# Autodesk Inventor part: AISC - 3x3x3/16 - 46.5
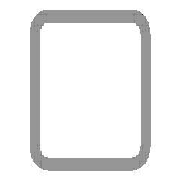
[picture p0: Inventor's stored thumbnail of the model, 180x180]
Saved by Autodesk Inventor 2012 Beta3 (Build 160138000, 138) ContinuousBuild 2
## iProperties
IsCustomPart: 1
Created: 2011-01
Part Number: AISC - 3x3x3/16 - 46.5
Material: Steel, Mild
Description: Tube
Document SubType Name: Modeling
Standard: ANSI
Designer: Beta-8540w
Standards Organization: ANSI
Language: en-US
Size Designation: 3x3x3/16
Categories: <MemberInstance><Categories><Category DisplayName="Structural Shapes" InternalName="089c4875-fa83-4c05-b084-43b9cc11f5ed" Mnemonic="GRDR"><CategoryParameter Dis
Stock Number: 3x3x3/16
Density: 7.86 g/cm^3
_CCFamilyMember: 9
_CCFamilyDisplayName: ANSI AISC (Square) - Tube
_FrameMemberDoc: Frame Member File
_Version: 15.0.0
_GetPNFromCC: 1
G_L: 46.500 in
G_W: 3.000 in
G_H: 3.000 in
+5DFD71D6-FECD-495E-A9B7-A5DCA39C5D65+CUTDETAIL1: Notch
Author: Beta-8540w
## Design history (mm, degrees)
node "Start plane"
node "End plane"
sketch "Sketch"
  geometry: L1 (-38.1, -28.575)-(-38.1, 28.575); L2 (-28.575, 38.1)-(28.575, 38.1); L3 (38.1, 28.575)-(38.1, -28.575); L4 (28.575, -38.1)-(-28.575, -38.1); L5 (-28.575, 33.337)-(28.575, 33.338); L6 (33.338, 28.575)-(33.338, -28.575); L7 (28.575, -33.337)-(-28.575, -33.338); L8 (-33.338, -28.575)-(-33.338, 28.575); L9 (0, 56.102)-(0, -56.102) reference; L10 (-56.102, 0)-(56.102, 0) reference; A1 r 9.525 centre (-28.575, -28.575) between (-38.1, -28.575) and (-28.575, -38.1); A2 r 9.525 centre (-28.575, 28.575) between (-28.575, 38.1) and (-38.1, 28.575); A3 r 9.525 centre (28.575, 28.575) between (38.1, 28.575) and (28.575, 38.1); A4 r 9.525 centre (28.575, -28.575) between (28.575, -38.1) and (38.1, -28.575); A5 r 4.763 centre (-28.575, 28.575) between (-28.575, 33.337) and (-33.338, 28.575); A6 r 4.763 centre (28.575, 28.575) between (33.338, 28.575) and (28.575, 33.338); A7 r 4.763 centre (28.575, -28.575) between (28.575, -33.337) and (33.338, -28.575); A8 r 4.763 centre (-28.575, -28.575) between (-33.338, -28.575) and (-28.575, -33.338)
  constraints: 16 end point, 16 point on circle, 8 centre point, 8 tangent, 4 parallel, 3 equal radius, 2 perpendicular, 7 other
  dimensions: "d10" = 76.2 distance between parallel lines of L2 L4 (= G_H); "d11" = 76.2 distance between parallel lines of L1 L3 (= G_W); "d12" = 4.7625 distance between parallel lines of L3 L6 (= G_T); "d15" = 38.1 distance between parallel lines of L2 L10 (= 0.5 x d10); "d16" = 38.1 distance between parallel lines of L9 L3 (= 0.5 x d11); "d17" = 9.525 radius of A1 (= G_IR)
extrude "Body" new body sketch "Sketch" stored distance "d3" = 1181.1 (= G_L); taper "d4" = 0 deg
node "Driven Length"
  sketch "Sketch3"
    geometry: L1 (0, 0)-(10, 0) reference
    constraints: 2 end point, 1 horizontal
  workplane "Work Plane3"
  sketch "Sketch4"
    geometry: L1 (-2, 38.1)-(12, 38.1) reference; L2 (-2, 1219.2)-(12, 1219.2) reference
    dimensions: "d19" = 1181.1 distance between parallel lines of L1 L2 (derived)
workplane "Work Plane4"
split "Split1"
workplane "Work Plane5"
workplane "Work Plane6"
workplane "Work Plane7"
sketch "Sketch5"
  geometry: L1 (-38.1, -28.575)-(-38.1, 28.575); L2 (-28.575, 38.1)-(28.575, 38.1); L3 (38.1, 28.575)-(38.1, -28.575); L4 (28.575, -38.1)-(-28.575, -38.1); L5 (-28.575, 33.337)-(28.575, 33.338); L6 (33.338, 28.575)-(33.338, -28.575); L7 (28.575, -33.337)-(-28.575, -33.338); L8 (-33.338, -28.575)-(-33.338, 28.575); A1 r 9.525 centre (-28.575, -28.575) between (-38.1, -28.575) and (-28.575, -38.1); A2 r 9.525 centre (-28.575, 28.575) between (-28.575, 38.1) and (-38.1, 28.575); A3 r 9.525 centre (28.575, 28.575) between (38.1, 28.575) and (28.575, 38.1); A4 r 9.525 centre (28.575, -28.575) between (28.575, -38.1) and (38.1, -28.575); A5 r 4.763 centre (-28.575, 28.575) between (-28.575, 33.337) and (-33.338, 28.575); A6 r 4.763 centre (28.575, 28.575) between (33.338, 28.575) and (28.575, 33.338); A7 r 4.763 centre (28.575, -28.575) between (28.575, -33.337) and (33.338, -28.575); A8 r 4.763 centre (-28.575, -28.575) between (-33.338, -28.575) and (-28.575, -33.338)
  constraints: 16 end point, 16 point on circle, 8 centre point
extrude "Extrusion2" cut sketch "Sketch5" stored distance "d20" = 3.302; taper "d21" = 0 deg
body "Solid1"
other parameters: "G_W" = 76.2 [user parameter; used in 1 equation term], "G_H" = 76.2 [user parameter; used in 1 equation term], "G_T" = 4.7625 [user parameter; used in 1 equation term], "G_IR" = 9.525 [user parameter; used in 1 equation term], "G_L" = 1181.1 (= d19) [user parameter; used in 1 equation term], "G_OFFSET_START" = -38.1 [user parameter; used in 1 equation term], "G_OFFSET_END" = 0 [user parameter; used in 1 equation term], "d13" = 38.1 (= -G_OFFSET_START), "d14" = 1219.2 (= G_OFFSET_END + B_L), "B_L" = 1219.2 [user parameter; used in 1 equation term], "d18" = 90 deg
